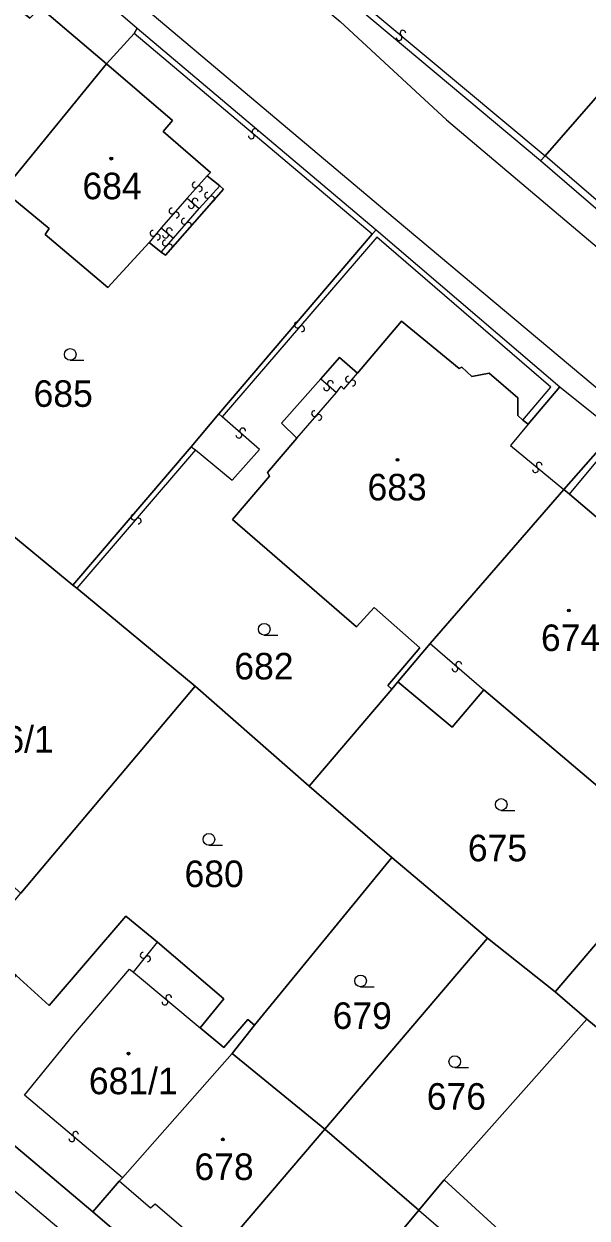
# Model space of a CAD drawing. Extents: x -600309 to -598967, y -1161267 to -1160292.
# Drawn here: x -599613.9 to -599577.8, y -1160422.7 to -1160346.2 of the extents above; entities that cross this region are included whole.
import ezdxf

# ---------------------------------------------------------------- set-up
doc = ezdxf.new("R2010")
doc.units = 0
for name, color, linetype in [('Level 1', 7, 'Continuous'), ('Level 13', 7, 'Continuous'), ('Level 3', 7, 'Continuous'), ('Level 4', 7, 'Continuous'), ('Level 5', 7, 'Continuous'), ('Level 60', 7, 'Continuous'), ('Vrstva 60', 7, 'Continuous')]:
    doc.layers.add(name, color=color, linetype=linetype)

msp = doc.modelspace()

# ---------------------------------------------------------------- linework, layer by layer
at = {"layer": 'Level 1'}
for points in [[(-599561.36, -1160332.7), (-599580.53, -1160354.68)], [(-599621.86, -1160333.45), (-599606.66, -1160346.5)], [(-599608.62, -1160348.79), (-599612.86, -1160345.17), (-599613.53, -1160345.86), (-599616.4, -1160343.53), (-599617.45, -1160344.84), (-599619.88, -1160342.89), (-599620.13, -1160343.2), (-599625.05, -1160339.01), (-599630.7, -1160345.76), (-599625.75, -1160349.91), (-599621.7, -1160345.71), (-599619.54, -1160347.44), (-599622.64, -1160351.29), (-599618.74, -1160354.53), (-599618.38, -1160354.25), (-599615.23, -1160356.89)], [(-599580.82, -1160355), (-599599.29, -1160339.53)], [(-599608.62, -1160348.79), (-599606.84, -1160346.83)], [(-599606.84, -1160346.83), (-599606.66, -1160346.5)], [(-599606.66, -1160346.5), (-599591.35, -1160359.41)], [(-599615.23, -1160356.89), (-599608.62, -1160348.79)], [(-599608.62, -1160348.79), (-599604.4, -1160352.42), (-599605, -1160353.12), (-599601.96, -1160355.73), (-599602.17, -1160355.95)], [(-599580.53, -1160354.68), (-599580.82, -1160355)], [(-599568.06, -1160365.99), (-599580.82, -1160355)], [(-599602.17, -1160355.95), (-599601.37, -1160356.6)], [(-599605.88, -1160360.21), (-599608.53, -1160363.1), (-599612.54, -1160359.7), (-599612.3, -1160359.33), (-599615.23, -1160356.89)], [(-599601.37, -1160356.6), (-599601.12, -1160356.8), (-599604.84, -1160361.02), (-599605.12, -1160360.83)], [(-599591.6, -1160359.69), (-599591.35, -1160359.41)], [(-599591.35, -1160359.41), (-599579.58, -1160369.45)], [(-599601.42, -1160371.19), (-599591.6, -1160359.69)], [(-599605.12, -1160360.83), (-599605.88, -1160360.21)], [(-599581.96, -1160371.59), (-599582.28, -1160371.29), (-599582.27, -1160370.17), (-599584.11, -1160368.58), (-599585.22, -1160368.8), (-599585.87, -1160368.2), (-599586.03, -1160368.29), (-599589.72, -1160365.26), (-599592.55, -1160368.58)], [(-599592.55, -1160368.58), (-599593.69, -1160367.59), (-599594.9, -1160368.94)], [(-599594.9, -1160368.94), (-599597.41, -1160371.79), (-599596.43, -1160372.75)], [(-599579.58, -1160369.45), (-599581.61, -1160371.85)], [(-599579.58, -1160369.45), (-599576.05, -1160372.29)], [(-599603.2, -1160373.3), (-599601.42, -1160371.19)], [(-599581.61, -1160371.85), (-599581.96, -1160371.59)], [(-599579.33, -1160376.04), (-599576.05, -1160372.29)], [(-599596.43, -1160372.75), (-599598.31, -1160374.94), (-599598.18, -1160375.18), (-599600.55, -1160377.94), (-599592.62, -1160384.83), (-599591.48, -1160383.58), (-599588.55, -1160386.16), (-599590.6, -1160388.58), (-599590.35, -1160388.81)], [(-599610.78, -1160382.16), (-599603.2, -1160373.3)], [(-599587.89, -1160385.89), (-599579.33, -1160376.04)], [(-599579.33, -1160376.04), (-599578.97, -1160376.32)], [(-599578.97, -1160376.32), (-599576.83, -1160378.14)], [(-599610.78, -1160382.16), (-599616.41, -1160377.52)], [(-599610.52, -1160382.34), (-599610.78, -1160382.16)], [(-599610.52, -1160382.34), (-599602.94, -1160388.62)], [(-599589.96, -1160388.34), (-599587.89, -1160385.89)], [(-599590.35, -1160388.81), (-599589.96, -1160388.34)], [(-599584.46, -1160388.85), (-599586.49, -1160391.24), (-599589.96, -1160388.34)], [(-599602.94, -1160388.62), (-599614.11, -1160401.87)], [(-599602.94, -1160388.62), (-599595.65, -1160395.03)], [(-599595.65, -1160395.03), (-599590.35, -1160388.81)], [(-599573.53, -1160392.36), (-599573.01, -1160392.81), (-599575.91, -1160396.09), (-599584.46, -1160388.85)], [(-599590.35, -1160399.59), (-599595.65, -1160395.03)], [(-599599.14, -1160410.31), (-599590.35, -1160399.59)], [(-599584.23, -1160404.76), (-599590.35, -1160399.59)], [(-599605.36, -1160405.01), (-599607.39, -1160403.34), (-599612.29, -1160409.07), (-599614.41, -1160407.14)], [(-599579.89, -1160408.19), (-599575.71, -1160403.27)], [(-599602.62, -1160410.48), (-599601.1, -1160408.63), (-599605.36, -1160405.01)], [(-599594.64, -1160416.98), (-599584.23, -1160404.76)], [(-599579.89, -1160408.19), (-599584.23, -1160404.76)], [(-599577.87, -1160409.94), (-599579.89, -1160408.19)], [(-599599.14, -1160410.31), (-599599.56, -1160409.95), (-599601.1, -1160411.75), (-599602.62, -1160410.48)], [(-599600.57, -1160412.14), (-599599.14, -1160410.31)], [(-599587, -1160420.23), (-599577.87, -1160409.94)], [(-599577.87, -1160409.94), (-599564.67, -1160420.81)], [(-599622.25, -1160411.52), (-599609.49, -1160422.27)], [(-599607.59, -1160420.1), (-599600.57, -1160412.14)], [(-599600.57, -1160412.14), (-599594.64, -1160416.98)], [(-599601.6, -1160425.13), (-599594.64, -1160416.98)], [(-599588.61, -1160422.17), (-599594.64, -1160416.98)], [(-599609.49, -1160422.27), (-599607.81, -1160420.3)], [(-599607.81, -1160420.3), (-599607.59, -1160420.1)], [(-599588.61, -1160422.17), (-599587, -1160420.23)], [(-599585.02, -1160425.28), (-599583.49, -1160423.41), (-599587, -1160420.23)], [(-599603.49, -1160427.42), (-599609.49, -1160422.27)], [(-599595.38, -1160430.3), (-599588.61, -1160422.17)]]:
    msp.add_lwpolyline(points, dxfattribs=at)
at = {"layer": 'Level 13'}
for centre, start, end in [((-599589.879, -1160347.101), 177.24906, 49.83906), ((-599589.64, -1160346.82), 357.46352, 229.56152), ((-599599.34, -1160353.4), 177.21399, 49.31199), ((-599599.101, -1160353.12), 356.99953, 229.58953), ((-599602.946, -1160356.536), 85.10473, 317.69473), ((-599602.674, -1160356.785), 265.31918, 137.41718), ((-599602.155, -1160357.195), 85.07925, 317.17724), ((-599603.19, -1160357.85), 176.92192, 49.51192), ((-599602.95, -1160357.57), 357.13638, 229.23437), ((-599601.884, -1160357.444), 264.86479, 137.45479), ((-599604.428, -1160358.208), 86.01508, 318.60508), ((-599604.152, -1160358.453), 266.22953, 138.32753), ((-599604.6, -1160359.47), 357.4959, 229.5939), ((-599603.638, -1160358.868), 86.401, 318.49899), ((-599603.362, -1160359.111), 266.18654, 138.77654), ((-599605.642, -1160359.633), 87.90244, 320.49244), ((-599605.358, -1160359.868), 268.11689, 140.21489), ((-599604.857, -1160360.256), 85.77918, 317.87718), ((-599604.839, -1160359.751), 177.28144, 49.87144), ((-599604.583, -1160360.503), 265.56472, 138.15472), ((-599596.399, -1160365.499), 86.38087, 318.97087), ((-599596.121, -1160365.742), 266.59532, 138.69332), ((-599594.278, -1160369.242), 356.30752, 228.40551), ((-599593.129, -1160368.969), 86.91051, 319.0085), ((-599592.85, -1160369.21), 266.69605, 139.28605), ((-599594.522, -1160369.518), 176.09306, 48.68306), ((-599595.298, -1160371.168), 86.45091, 318.5489), ((-599595.021, -1160371.411), 266.23645, 138.82645), ((-599600.143, -1160372.557), 175.94907, 48.04706), ((-599599.898, -1160372.283), 355.73461, 228.32461), ((-599581.148, -1160374.761), 177.46859, 50.05859), ((-599580.911, -1160374.479), 357.68304, 229.78104), ((-599606.859, -1160377.799), 86.50371, 319.09371), ((-599606.581, -1160378.041), 266.71817, 138.81616), ((-599586.301, -1160387.509), 176.36495, 48.95495), ((-599586.058, -1160387.231), 356.5794, 228.6774), ((-599606.273, -1160405.843), 88.4941, 320.5921), ((-599605.987, -1160406.076), 268.27964, 140.86964), ((-599604.878, -1160408.841), 177.40542, 49.99542), ((-599604.641, -1160408.559), 357.61987, 229.71787), ((-599610.84, -1160417.59), 177.16506, 49.26306), ((-599610.601, -1160417.31), 356.95061, 229.54061)]:
    msp.add_arc(centre, 0.184, start, end, dxfattribs=at)
at = {"layer": 'Level 3'}
for points in [[(-599524.82, -1160413.53), (-599530.1, -1160409.12), (-599549.58, -1160392.72), (-599590.8, -1160358.17), (-599615.33, -1160337.5), (-599632.67, -1160322.41), (-599636.51, -1160318.59), (-599655.89, -1160297.57), (-599660.657, -1160292.347)], [(-599651.497, -1160292.347), (-599644.77, -1160299.72), (-599634.15, -1160310.33), (-599627.62, -1160316.76), (-599618.38, -1160325.68), (-599605.71, -1160335.98), (-599593.66, -1160346.07), (-599586.85, -1160352.37), (-599554.88, -1160379.39), (-599522.21, -1160406.42)], [(-599598.99, -1160339.24), (-599580.53, -1160354.68)], [(-599591.6, -1160359.69), (-599606.84, -1160346.83)], [(-599698.81, -1160347.45), (-599698.8, -1160347.76), (-599698.67, -1160348.55), (-599698.38, -1160349.34), (-599697.65, -1160350.63), (-599669.96, -1160374.11), (-599645.48, -1160394.78), (-599613.44, -1160421.83), (-599584.31, -1160446.38), (-599566.3, -1160461.83), (-599522.39, -1160498.3), (-599521.56, -1160498.85), (-599520.6, -1160499.11), (-599519.58, -1160499.15), (-599518.68, -1160498.85), (-599517.76, -1160498.26)], [(-599567.8, -1160365.63), (-599580.53, -1160354.68)], [(-599602.17, -1160355.95), (-599603.46, -1160357.38)], [(-599602.68, -1160358.04), (-599601.37, -1160356.6)], [(-599603.46, -1160357.38), (-599605.12, -1160359.28)], [(-599603.46, -1160357.38), (-599602.68, -1160358.04)], [(-599604.33, -1160359.94), (-599602.68, -1160358.04)], [(-599605.12, -1160359.28), (-599605.88, -1160360.21)], [(-599605.12, -1160359.28), (-599604.33, -1160359.94)], [(-599605.12, -1160360.83), (-599604.33, -1160359.94)], [(-599581.96, -1160371.59), (-599580.17, -1160369.49), (-599591.3, -1160359.88), (-599601.21, -1160371.37)], [(-599593.89, -1160369.82), (-599593.6, -1160369.42), (-599593.42, -1160369.6), (-599592.55, -1160368.58)], [(-599594.9, -1160368.94), (-599593.89, -1160369.82)], [(-599596.43, -1160372.75), (-599593.89, -1160369.82)], [(-599602.92, -1160373.49), (-599600.57, -1160375.44), (-599598.83, -1160373.47), (-599601.21, -1160371.37)], [(-599601.21, -1160371.37), (-599601.42, -1160371.19)], [(-599581.61, -1160371.85), (-599582.74, -1160373.21), (-599579.33, -1160376.04)], [(-599578.97, -1160376.32), (-599576.01, -1160372.77), (-599573.89, -1160374.58)], [(-599602.92, -1160373.49), (-599610.52, -1160382.34)], [(-599603.2, -1160373.3), (-599602.92, -1160373.49)], [(-599587.89, -1160385.89), (-599584.46, -1160388.85)], [(-599606.9, -1160406.92), (-599605.36, -1160405.01)], [(-599607.59, -1160420.1), (-599613.86, -1160414.8), (-599610.72, -1160410.92), (-599607.15, -1160406.73), (-599606.9, -1160406.92)], [(-599606.9, -1160406.92), (-599602.62, -1160410.48)], [(-599601.6, -1160425.13), (-599605.51, -1160421.78), (-599605.8, -1160422.04), (-599607.81, -1160420.3)], [(-599588.61, -1160422.17), (-599585.02, -1160425.28)]]:
    msp.add_lwpolyline(points, dxfattribs=at)
at = {"layer": 'Level 5'}
for p, q in [((-599610.94, -1160367.76), (-599610.065, -1160367.76)), ((-599598.52, -1160385.35), (-599597.645, -1160385.35)), ((-599583.34, -1160396.57), (-599582.465, -1160396.57)), ((-599602.06, -1160398.8), (-599601.185, -1160398.8)), ((-599592.35, -1160407.86), (-599591.475, -1160407.86)), ((-599586.32, -1160413.03), (-599585.445, -1160413.03))]:
    msp.add_line(p, q, dxfattribs=at)
for centre, radius in [((-599608.31, -1160354.85), 0.09), ((-599608.31, -1160354.85), 0.0521), ((-599610.94, -1160367.385), 0.375), ((-599589.98, -1160374.13), 0.09), ((-599589.98, -1160374.13), 0.0521), ((-599579.01, -1160383.77), 0.09), ((-599579.01, -1160383.77), 0.0521), ((-599598.52, -1160384.975), 0.375), ((-599583.34, -1160396.195), 0.375), ((-599602.06, -1160398.425), 0.375), ((-599592.35, -1160407.485), 0.375), ((-599607.21, -1160412.14), 0.09), ((-599607.21, -1160412.14), 0.0521), ((-599586.32, -1160412.655), 0.375), ((-599601.17, -1160417.63), 0.09), ((-599601.17, -1160417.63), 0.0521)]:
    msp.add_circle(centre, radius, dxfattribs=at)
at = {"layer": 'Level 60'}
for points in [[(-599561.36, -1160332.7), (-599580.53, -1160354.68), (-599580.82, -1160355), (-599599.29, -1160339.53)], [(-599568.06, -1160365.99), (-599580.82, -1160355), (-599580.53, -1160354.68), (-599561.36, -1160332.7)], [(-599621.86, -1160333.45), (-599606.66, -1160346.5), (-599606.84, -1160346.83), (-599608.62, -1160348.79), (-599612.86, -1160345.17)], [(-599679.63, -1160363.13), (-599660.57, -1160379.26), (-599656.66, -1160382.54), (-599647.52, -1160390.21), (-599641.54, -1160395.24), (-599635.45, -1160400.37), (-599622.25, -1160411.52), (-599609.49, -1160422.27), (-599603.49, -1160427.42)], [(-599576.83, -1160378.14), (-599578.97, -1160376.32), (-599579.33, -1160376.04), (-599576.05, -1160372.29)], [(-599575.71, -1160403.27), (-599579.89, -1160408.19), (-599584.23, -1160404.76), (-599590.35, -1160399.59), (-599595.65, -1160395.03), (-599590.35, -1160388.81), (-599589.96, -1160388.34), (-599586.49, -1160391.24), (-599584.46, -1160388.85), (-599575.91, -1160396.09)]]:
    msp.add_lwpolyline(points, dxfattribs=at)
for points in [[(-599608.62, -1160348.79), (-599615.23, -1160356.89), (-599618.38, -1160354.25), (-599618.74, -1160354.53), (-599622.64, -1160351.29), (-599619.54, -1160347.44), (-599621.7, -1160345.71), (-599625.75, -1160349.91), (-599630.7, -1160345.76), (-599625.05, -1160339.01), (-599620.13, -1160343.2), (-599619.88, -1160342.89), (-599617.45, -1160344.84), (-599616.4, -1160343.53), (-599613.53, -1160345.86), (-599612.86, -1160345.17)], [(-599603.2, -1160373.3), (-599610.78, -1160382.16), (-599616.41, -1160377.52), (-599622.43, -1160372.39), (-599626.07, -1160369.33), (-599615.23, -1160356.89), (-599612.3, -1160359.33), (-599612.54, -1160359.7), (-599608.53, -1160363.1), (-599605.88, -1160360.21), (-599605.12, -1160360.83), (-599604.84, -1160361.02), (-599601.12, -1160356.8), (-599601.37, -1160356.6), (-599602.17, -1160355.95), (-599601.96, -1160355.73), (-599605, -1160353.12), (-599604.4, -1160352.42), (-599608.62, -1160348.79), (-599606.84, -1160346.83), (-599606.66, -1160346.5), (-599591.35, -1160359.41), (-599591.6, -1160359.69), (-599601.42, -1160371.19)], [(-599604.4, -1160352.42), (-599605, -1160353.12), (-599601.96, -1160355.73), (-599602.17, -1160355.95), (-599601.37, -1160356.6), (-599601.12, -1160356.8), (-599604.84, -1160361.02), (-599605.12, -1160360.83), (-599605.88, -1160360.21), (-599608.53, -1160363.1), (-599612.54, -1160359.7), (-599612.3, -1160359.33), (-599615.23, -1160356.89), (-599608.62, -1160348.79)], [(-599590.35, -1160388.81), (-599595.65, -1160395.03), (-599602.94, -1160388.62), (-599610.52, -1160382.34), (-599610.78, -1160382.16), (-599603.2, -1160373.3), (-599601.42, -1160371.19), (-599591.6, -1160359.69), (-599591.35, -1160359.41), (-599579.58, -1160369.45), (-599581.61, -1160371.85), (-599581.96, -1160371.59), (-599582.28, -1160371.29), (-599582.27, -1160370.17), (-599584.11, -1160368.58), (-599585.22, -1160368.8), (-599585.87, -1160368.2), (-599586.03, -1160368.29), (-599589.72, -1160365.26), (-599592.55, -1160368.58), (-599593.69, -1160367.59), (-599594.9, -1160368.94), (-599597.41, -1160371.79), (-599596.43, -1160372.75), (-599598.31, -1160374.94), (-599598.18, -1160375.18), (-599600.55, -1160377.94), (-599592.62, -1160384.83), (-599591.48, -1160383.58), (-599588.55, -1160386.16), (-599590.6, -1160388.58)], [(-599587.89, -1160385.89), (-599589.96, -1160388.34), (-599590.35, -1160388.81), (-599590.6, -1160388.58), (-599588.55, -1160386.16), (-599591.48, -1160383.58), (-599592.62, -1160384.83), (-599600.55, -1160377.94), (-599598.18, -1160375.18), (-599598.31, -1160374.94), (-599596.43, -1160372.75), (-599597.41, -1160371.79), (-599594.9, -1160368.94), (-599593.69, -1160367.59), (-599592.55, -1160368.58), (-599589.72, -1160365.26), (-599586.03, -1160368.29), (-599585.87, -1160368.2), (-599585.22, -1160368.8), (-599584.11, -1160368.58), (-599582.27, -1160370.17), (-599582.28, -1160371.29), (-599581.96, -1160371.59), (-599581.61, -1160371.85), (-599579.58, -1160369.45), (-599576.05, -1160372.29), (-599579.33, -1160376.04)], [(-599579.33, -1160376.04), (-599578.97, -1160376.32), (-599576.83, -1160378.14), (-599576.53, -1160378.43), (-599572.82, -1160381.49), (-599571.4, -1160381.14), (-599569.38, -1160382.86), (-599569.58, -1160384.19), (-599568.98, -1160384.81), (-599570.94, -1160387.23), (-599570.22, -1160387.88), (-599569.88, -1160388.14), (-599573.53, -1160392.36), (-599573.01, -1160392.81), (-599575.91, -1160396.09), (-599584.46, -1160388.85), (-599586.49, -1160391.24), (-599589.96, -1160388.34), (-599587.89, -1160385.89)], [(-599610.78, -1160382.16), (-599610.52, -1160382.34), (-599602.94, -1160388.62), (-599614.11, -1160401.87), (-599616.69, -1160399.6), (-599623.02, -1160406.94), (-599620.33, -1160409.25), (-599622.25, -1160411.52), (-599635.45, -1160400.37), (-599633.79, -1160398.37), (-599633.59, -1160398.09), (-599627.43, -1160403.3), (-599624.31, -1160399.63), (-599623.34, -1160400.37), (-599621.77, -1160398.51), (-599622.65, -1160397.72), (-599620.68, -1160395.32), (-599626.92, -1160390.06), (-599626.73, -1160389.85), (-599616.41, -1160377.52)], [(-599564.3, -1160421.12), (-599564.67, -1160420.81), (-599577.87, -1160409.94), (-599579.89, -1160408.19), (-599575.71, -1160403.27), (-599572.51, -1160405.93), (-599568.63, -1160401.29), (-599571.87, -1160398.67), (-599570.38, -1160396.86), (-599560.89, -1160385.52), (-599560.59, -1160385.19), (-599545.16, -1160398.21), (-599545.43, -1160398.54)], [(-599595.65, -1160395.03), (-599590.35, -1160399.59), (-599599.14, -1160410.31), (-599599.56, -1160409.95), (-599601.1, -1160411.75), (-599602.62, -1160410.48), (-599601.1, -1160408.63), (-599605.36, -1160405.01), (-599607.39, -1160403.34), (-599612.29, -1160409.07), (-599614.41, -1160407.14), (-599616.84, -1160405.1), (-599614.11, -1160401.87), (-599602.94, -1160388.62)], [(-599590.35, -1160399.59), (-599584.23, -1160404.76), (-599594.64, -1160416.98), (-599600.57, -1160412.14), (-599599.14, -1160410.31)], [(-599607.81, -1160420.3), (-599609.49, -1160422.27), (-599622.25, -1160411.52), (-599620.33, -1160409.25), (-599617.98, -1160411.23), (-599614.41, -1160407.14), (-599612.29, -1160409.07), (-599607.39, -1160403.34), (-599605.36, -1160405.01), (-599601.1, -1160408.63), (-599602.62, -1160410.48), (-599601.1, -1160411.75), (-599599.56, -1160409.95), (-599599.14, -1160410.31), (-599600.57, -1160412.14), (-599607.59, -1160420.1)], [(-599587, -1160420.23), (-599588.61, -1160422.17), (-599594.64, -1160416.98), (-599584.23, -1160404.76), (-599579.89, -1160408.19), (-599577.87, -1160409.94)], [(-599564.67, -1160420.81), (-599568.33, -1160425.25), (-599582.09, -1160441.47), (-599584.06, -1160443.74), (-599597.32, -1160432.69), (-599595.59, -1160430.61), (-599595.38, -1160430.3), (-599589.13, -1160435.6), (-599587.99, -1160436.56), (-599585.55, -1160433.88), (-599585.31, -1160434.09), (-599580.77, -1160429.05), (-599582.1, -1160427.9), (-599585.02, -1160425.28), (-599583.49, -1160423.41), (-599587, -1160420.23), (-599577.87, -1160409.94)], [(-599601.6, -1160425.13), (-599603.49, -1160427.42), (-599609.49, -1160422.27), (-599607.81, -1160420.3), (-599607.59, -1160420.1), (-599600.57, -1160412.14), (-599594.64, -1160416.98)], [(-599588.61, -1160422.17), (-599595.38, -1160430.3), (-599595.59, -1160430.61), (-599597.32, -1160432.69), (-599603.49, -1160427.42), (-599601.6, -1160425.13), (-599594.64, -1160416.98)], [(-599583.49, -1160423.41), (-599585.02, -1160425.28), (-599582.1, -1160427.9), (-599580.77, -1160429.05), (-599585.31, -1160434.09), (-599585.55, -1160433.88), (-599587.99, -1160436.56), (-599589.13, -1160435.6), (-599595.38, -1160430.3), (-599588.61, -1160422.17), (-599587, -1160420.23)]]:
    msp.add_lwpolyline(points, close=True, dxfattribs=at)
at = {"layer": 'Vrstva 60'}
msp.add_lwpolyline([(-599568.06, -1160365.99), (-599580.82, -1160355), (-599599.29, -1160339.53), (-599614.1, -1160327.04), (-599619.62, -1160321.95), (-599628.56, -1160313.84), (-599635.12, -1160307.15), (-599642.02, -1160299.92), (-599648.854, -1160292.347), (-599662.269, -1160292.347), (-599657.14, -1160298.06), (-599650.91, -1160305.2), (-599640.07, -1160316.64), (-599634.14, -1160322.75), (-599626.81, -1160329.46), (-599621.86, -1160333.45), (-599606.66, -1160346.5), (-599591.35, -1160359.41), (-599579.58, -1160369.45), (-599576.05, -1160372.29)], dxfattribs=at)

# ---------------------------------------------------------------- texts
at = {"layer": 'Level 4'}
for s, p in [('684', (-599610.158, -1160357.45)), ('685', (-599613.289, -1160370.74)), ('683', (-599591.905, -1160376.73)), ('674', (-599580.799, -1160386.37)), ('682', (-599600.433, -1160388.19)), ('686/1', (-599617.686, -1160392.87)), ('675', (-599585.48, -1160399.83)), ('680', (-599603.621, -1160401.48)), ('679', (-599594.139, -1160410.56)), ('681/1', (-599609.749, -1160414.74)), ('676', (-599588.109, -1160415.73)), ('678', (-599602.986, -1160420.23))]:
    msp.add_text(s, height=1.7, dxfattribs=at).set_placement(p)

doc.saveas('drawing.dxf')
